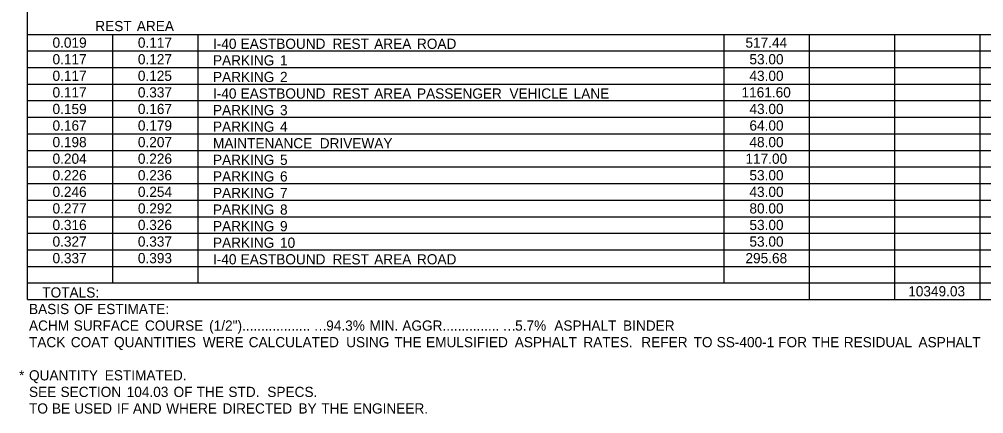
# Model space of a CAD drawing. Extents: x 2261867 to 2275370, y -3124789 to -3122260.
# Drawn here: x 2269376 to 2269943, y -3123501 to -3123269 of the extents above; entities that cross this region are included whole.
import ezdxf

# ---------------------------------------------------------------- set-up
doc = ezdxf.new("R2010")
doc.units = 0
doc.layers.add('Default', color=7, linetype='Continuous')

msp = doc.modelspace()

# ---------------------------------------------------------------- linework, layer by layer
at = {"layer": 'Default'}
for p, q in [((2269380.47, -3123434.1), (2269380.47, -3122273.85)), ((2269380.47, -3123434.1), (2269380.47, -3122273.85)), ((2269380.47, -3123278.1), (2270507.08, -3123278.1)), ((2269430.68, -3123414.6), (2269430.68, -3123278.1)), ((2269430.68, -3123424.35), (2269430.68, -3123278.1)), ((2269480.89, -3123424.35), (2269480.89, -3123278.1)), ((2269480.89, -3123424.35), (2269480.89, -3123278.1)), ((2269790.46, -3123424.35), (2269790.46, -3123278.1)), ((2269790.46, -3123424.35), (2269790.46, -3123278.1)), ((2269840.67, -3123307.35), (2269840.67, -3123278.1)), ((2269840.67, -3123434.1), (2269840.67, -3123278.1)), ((2269890.88, -3123414.6), (2269890.88, -3123278.1)), ((2269890.88, -3123434.1), (2269890.88, -3123278.1)), ((2269941.09, -3123307.35), (2269941.09, -3123278.1)), ((2269941.09, -3123434.1), (2269941.09, -3123278.1)), ((2269380.47, -3123287.85), (2270507.08, -3123287.85)), ((2269380.47, -3123297.6), (2270507.08, -3123297.6)), ((2269380.47, -3123307.35), (2270507.08, -3123307.35)), ((2269380.47, -3123317.1), (2270507.08, -3123317.1)), ((2269840.67, -3123404.85), (2269840.67, -3123317.1)), ((2269941.09, -3123404.85), (2269941.09, -3123317.1)), ((2269380.47, -3123326.85), (2270507.08, -3123326.85)), ((2269380.47, -3123336.6), (2270507.08, -3123336.6)), ((2269380.47, -3123346.35), (2270507.08, -3123346.35)), ((2269380.47, -3123356.1), (2270507.08, -3123356.1)), ((2269380.47, -3123365.85), (2270507.08, -3123365.85)), ((2269380.47, -3123375.6), (2270507.08, -3123375.6)), ((2269380.47, -3123385.35), (2270507.08, -3123385.35)), ((2269380.47, -3123395.1), (2270507.08, -3123395.1)), ((2269380.47, -3123404.85), (2270507.08, -3123404.85)), ((2269380.47, -3123414.6), (2270507.08, -3123414.6)), ((2269380.47, -3123424.35), (2270507.08, -3123424.35)), ((2269480.89, -3123424.35), (2269790.46, -3123424.35)), ((2269790.46, -3123424.35), (2269941.09, -3123424.35)), ((2269840.67, -3123434.1), (2269840.67, -3123424.35)), ((2269941.09, -3123424.35), (2269991.31, -3123424.35)), ((2269380.47, -3123434.1), (2270507.08, -3123434.1))]:
    msp.add_line(p, q, dxfattribs=at)

# ---------------------------------------------------------------- texts
for s, p in [('REST', (2269420.44, -3123276.22)), (' AREA', (2269442.63, -3123276.22)), ('0.019', (2269395.28, -3123285.97)), ('0.117', (2269445.49, -3123285.97)), ('I-40', (2269489.67, -3123286.65)), (' EASTBOUND', (2269503.7, -3123286.65)), (' REST', (2269557.76, -3123286.65)), (' AREA', (2269582.28, -3123286.65)), (' ROAD', (2269607.46, -3123286.65)), ('517.44', (2269802.95, -3123285.97)), ('0.117', (2269395.28, -3123295.72)), ('0.127', (2269445.49, -3123295.72)), ('PARKING', (2269489.67, -3123296.4)), (' 1', (2269526.88, -3123296.4)), ('53.00', (2269805.28, -3123295.72)), ('0.117', (2269395.28, -3123305.47)), ('0.125', (2269445.47, -3123305.47)), ('PARKING', (2269489.67, -3123306.15)), (' 2', (2269526.88, -3123306.15)), ('43.00', (2269805.28, -3123305.47)), ('0.117', (2269395.28, -3123315.22)), ('0.337', (2269445.49, -3123315.22)), ('I-40', (2269489.67, -3123315.9)), (' EASTBOUND', (2269503.7, -3123315.9)), (' REST', (2269557.76, -3123315.9)), (' PASSENGER', (2269607.46, -3123315.9)), (' VEHICLE', (2269661.86, -3123315.9)), ('1161.60', (2269800.62, -3123315.22)), (' AREA', (2269582.28, -3123315.9)), (' LANE', (2269699.62, -3123315.9)), ('0.159', (2269395.28, -3123324.97)), ('0.167', (2269445.49, -3123324.97)), ('PARKING', (2269489.67, -3123325.65)), (' 3', (2269526.88, -3123325.65)), ('43.00', (2269805.28, -3123324.97)), ('0.167', (2269395.28, -3123334.72)), ('0.179', (2269445.49, -3123334.72)), ('PARKING', (2269489.67, -3123335.4)), (' 4', (2269526.88, -3123335.4)), ('64.00', (2269805.28, -3123334.72)), ('0.198', (2269395.28, -3123344.47)), ('0.207', (2269445.49, -3123344.47)), ('MAINTENANCE', (2269489.67, -3123345.15)), (' DRIVEWAY', (2269550.25, -3123345.15)), ('48.00', (2269805.28, -3123344.47)), ('0.204', (2269395.29, -3123354.22)), ('0.226', (2269445.49, -3123354.22)), ('PARKING', (2269489.67, -3123354.9)), (' 5', (2269526.88, -3123354.9)), ('117.00', (2269802.95, -3123354.22)), ('0.226', (2269395.28, -3123363.97)), ('0.236', (2269445.49, -3123363.97)), ('PARKING', (2269489.67, -3123364.65)), (' 6', (2269526.88, -3123364.65)), ('53.00', (2269805.28, -3123363.97)), ('0.246', (2269395.28, -3123373.72)), ('0.254', (2269445.51, -3123373.72)), ('PARKING', (2269489.67, -3123374.4)), (' 7', (2269526.88, -3123374.4)), ('43.00', (2269805.28, -3123373.72)), ('0.277', (2269395.28, -3123383.47)), ('0.292', (2269445.53, -3123383.47)), ('80.00', (2269805.28, -3123383.47)), ('PARKING', (2269489.67, -3123384.15)), (' 8', (2269526.88, -3123384.15)), ('0.316', (2269395.28, -3123393.22)), ('0.326', (2269445.49, -3123393.22)), ('PARKING', (2269489.67, -3123393.9)), (' 9', (2269526.88, -3123393.9)), ('53.00', (2269805.28, -3123393.22)), ('0.327', (2269395.28, -3123402.97)), ('0.337', (2269445.49, -3123402.97)), ('PARKING', (2269489.67, -3123403.65)), (' 10', (2269526.88, -3123403.65)), ('53.00', (2269805.28, -3123402.97)), ('0.337', (2269395.28, -3123412.72)), ('0.393', (2269445.49, -3123412.72)), ('I-40', (2269489.67, -3123413.4)), (' EASTBOUND', (2269503.7, -3123413.4)), (' REST', (2269557.76, -3123413.4)), (' AREA', (2269582.28, -3123413.4)), (' ROAD', (2269607.46, -3123413.4)), ('295.68', (2269802.93, -3123412.72)), ('TOTALS:', (2269389.24, -3123432.9)), ('10349.03', (2269898.69, -3123432.22)), ('BASIS', (2269381.44, -3123442.65)), (' OF', (2269405.7, -3123442.65)), (' ESTIMATE:', (2269419.29, -3123442.65)), ('ACHM', (2269381.44, -3123452.4)), (' SURFACE', (2269405.5, -3123452.4)), (' COURSE', (2269447.44, -3123452.4)), (' (1/2")..................', (2269485.2, -3123452.4)), ('…', (2269548.9, -3123452.4)), ('94.3%', (2269556.29, -3123452.4)), (' MIN.', (2269579.54, -3123452.4)), (' AGGR...............', (2269598.83, -3123452.4)), ('…', (2269660.03, -3123452.4)), ('5.7%', (2269667.43, -3123452.4)), ('  ASPHALT', (2269686.01, -3123452.4)), (' BINDER', (2269728.7, -3123452.4)), ('TACK', (2269381.44, -3123462.15)), (' COAT', (2269403.79, -3123462.15)), (' QUANTITIES', (2269429.24, -3123462.15)), (' WERE', (2269481.44, -3123462.15)), (' CALCULATED', (2269508.47, -3123462.15)), (' USING', (2269565.79, -3123462.15)), (' THE', (2269594.14, -3123462.15)), (' EMULSIFIED', (2269612.79, -3123462.15)), (' ASPHALT', (2269664.98, -3123462.15)), (' RATES.', (2269705.35, -3123462.15)), ('  REFER', (2269737.23, -3123462.15)), (' TO', (2269770.19, -3123462.15)), (' SS-400-1', (2269783.78, -3123462.15)), (' FOR', (2269819.97, -3123462.15)), (' THE', (2269839.89, -3123462.15)), (' RESIDUAL', (2269858.54, -3123462.15)), (' ASPHALT', (2269902.5, -3123462.15)), ('*', (2269375.59, -3123481.65)), ('QUANTITY', (2269381.44, -3123481.65)), (' ESTIMATED.', (2269423.77, -3123481.65)), ('SEE', (2269381.44, -3123491.4)), (' SECTION', (2269397.77, -3123491.4)), (' 104.03', (2269436.68, -3123491.4)), (' OF', (2269464.26, -3123491.4)), (' THE', (2269477.85, -3123491.4)), (' STD.', (2269496.5, -3123491.4)), ('  SPECS.', (2269517.19, -3123491.4)), ('TO', (2269381.44, -3123501.15)), (' BE', (2269392.71, -3123501.15)), (' USED', (2269405.78, -3123501.15)), (' IF', (2269430.95, -3123501.15)), (' AND', (2269440.35, -3123501.15)), (' WHERE', (2269459.93, -3123501.15)), (' DIRECTED', (2269493.02, -3123501.15)), (' BY', (2269537.75, -3123501.15)), (' THE', (2269551.2, -3123501.15)), (' ENGINEER.', (2269569.85, -3123501.15))]:
    msp.add_text(s, height=6, dxfattribs=at).set_placement(p)

doc.saveas('drawing.dxf')
